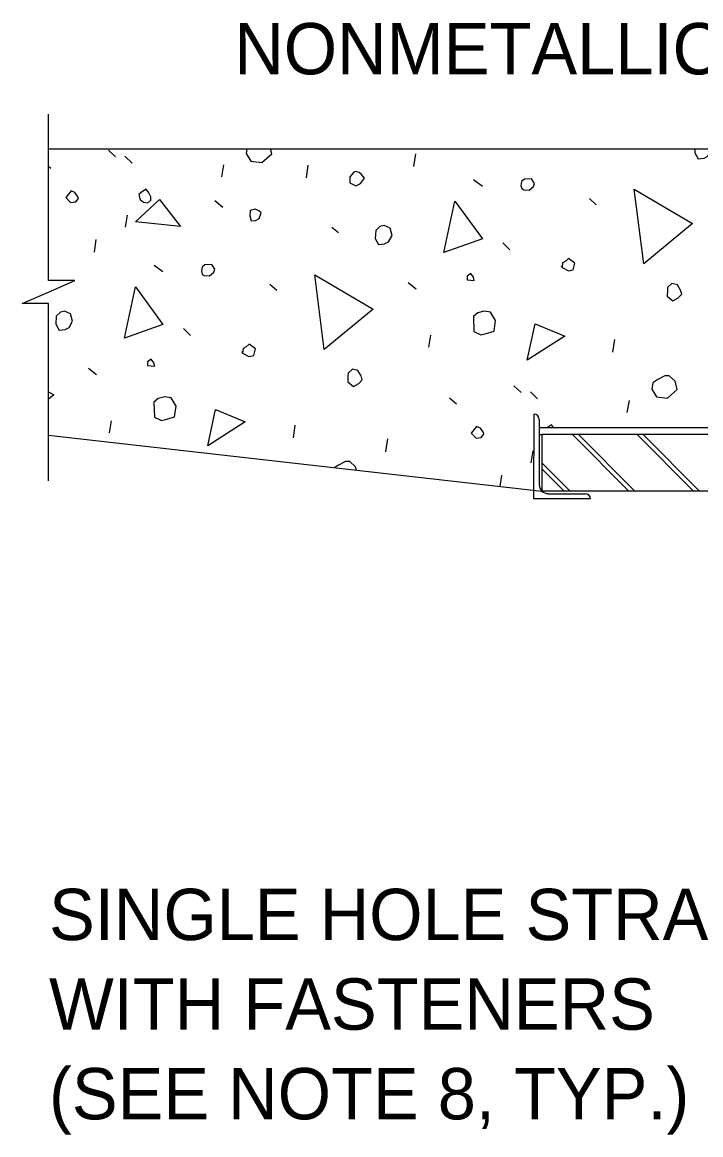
# Model space of a CAD drawing. Extents: x -1660015.2 to -1659984.9, y 2580594.2 to 2580616.7.
# Drawn here: x -1660015.124 to -1660013.123, y 2580601.152 to 2580604.429 of the extents above; entities that cross this region are included whole.
import ezdxf

# ---------------------------------------------------------------- set-up
doc = ezdxf.new("R2010")
doc.units = 0
for name, color, linetype in [('Miscellaneous', 7, 'Continuous'), ('Miscellaneous3', 7, 'Continuous'), ('PlotBorder_dp', 7, 'Continuous'), ('SheetLines_dp', 7, 'Continuous'), ('SteelGirder', 7, 'Continuous')]:
    doc.layers.add(name, color=color, linetype=linetype)

msp = doc.modelspace()

# ---------------------------------------------------------------- linework, layer by layer
at = {"layer": 'Miscellaneous'}
for p, q in [((-1660014.8697, 2580604.0526), (-1660014.8487, 2580604.0323)), ((-1660014.8209, 2580604.0346), (-1660014.7999, 2580604.0144)), ((-1660013.9689, 2580604.0041), (-1660013.9635, 2580604.0418)), ((-1660015.0462, 2580604.0056), (-1660015.0392, 2580603.9994)), ((-1660014.5354, 2580603.9739), (-1660014.5294, 2580604.0092)), ((-1660014.2861, 2580603.9709), (-1660014.2807, 2580604.0085)), ((-1660013.793, 2580603.9658), (-1660013.7673, 2580603.9468)), ((-1660014.5555, 2580603.9039), (-1660014.5321, 2580603.8842)), ((-1660013.4519, 2580603.9097), (-1660013.4316, 2580603.8918)), ((-1660014.8192, 2580603.8254), (-1660014.8131, 2580603.8607)), ((-1660014.2109, 2580603.8254), (-1660014.1913, 2580603.8099)), ((-1660014.9107, 2580603.7517), (-1660014.9053, 2580603.7894)), ((-1660013.7068, 2580603.7793), (-1660013.6859, 2580603.759)), ((-1660014.7348, 2580603.7135), (-1660014.709, 2580603.6945)), ((-1660014.3937, 2580603.6573), (-1660014.3734, 2580603.6395)), ((-1660013.9862, 2580603.663), (-1660013.9629, 2580603.6434)), ((-1660014.6486, 2580603.5269), (-1660014.6276, 2580603.5066)), ((-1660013.9248, 2580603.4724), (-1660013.9187, 2580603.5077)), ((-1660013.3824, 2580603.4573), (-1660013.377, 2580603.4949)), ((-1660014.928, 2580603.4106), (-1660014.9046, 2580603.391)), ((-1660013.6743, 2580603.3583), (-1660013.6533, 2580603.3381)), ((-1660013.6255, 2580603.3404), (-1660013.6045, 2580603.3201)), ((-1660013.8641, 2580603.323), (-1660013.8438, 2580603.3052)), ((-1660013.34, 2580603.2797), (-1660013.3339, 2580603.3149)), ((-1660013.6151, 2580603.0247), (-1660013.615, 2580603.2747)), ((-1660014.8666, 2580603.22), (-1660014.8605, 2580603.2553)), ((-1660014.3242, 2580603.2049), (-1660014.3188, 2580603.2426)), ((-1660013.5994, 2580603.2591), (-1660013.5994, 2580603.0664)), ((-1660013.5994, 2580603.2354), (-1660012.0917, 2580603.2354)), ((-1660013.5994, 2580603.2146), (-1660013.5918, 2580603.2146)), ((-1660013.3353, 2580603.0479), (-1660013.502, 2580603.2147)), ((-1660013.3176, 2580603.0479), (-1660013.4843, 2580603.2147)), ((-1660013.1444, 2580603.0479), (-1660013.3111, 2580603.2147)), ((-1660013.1267, 2580603.0479), (-1660013.2934, 2580603.2147)), ((-1660014.0518, 2580603.164), (-1660014.0464, 2580603.2017)), ((-1660013.6238, 2580603.1312), (-1660013.6177, 2580603.1665)), ((-1660013.5085, 2580603.0479), (-1660013.5918, 2580603.1312)), ((-1660013.5262, 2580603.0479), (-1660013.5918, 2580603.1135)), ((-1660013.7147, 2580603.0619), (-1660013.7099, 2580603.0952)), ((-1660013.4484, 2580603.0247), (-1660013.6151, 2580603.0247)), ((-1660013.5734, 2580603.0403), (-1660013.464, 2580603.0403))]:
    msp.add_line(p, q, dxfattribs=at)
for points in [[(-1660014.4632, 2580604.0425), (-1660014.4495, 2580604.0203), (-1660014.4173, 2580604.0159), (-1660014.388, 2580604.0419), (-1660014.3918, 2580604.0559)], [(-1660014.4613, 2580604.0559), (-1660014.4632, 2580604.0425)], [(-1660013.1406, 2580604.0559), (-1660013.1412, 2580604.0447), (-1660013.1312, 2580604.0267), (-1660013.1137, 2580604.0288), (-1660013.1023, 2580604.0344), (-1660013.0917, 2580604.0528), (-1660013.0925, 2580604.0559)], [(-1660014.1576, 2580603.9742), (-1660014.1579, 2580603.956), (-1660014.1402, 2580603.9478), (-1660014.1264, 2580603.9541), (-1660014.1151, 2580603.9701), (-1660014.1232, 2580603.9809), (-1660014.13, 2580603.9868), (-1660014.1409, 2580603.9891), (-1660014.1457, 2580603.9878), (-1660014.1576, 2580603.9742)], [(-1660013.6513, 2580603.9391), (-1660013.6452, 2580603.9355), (-1660013.6294, 2580603.9346), (-1660013.6168, 2580603.9457), (-1660013.614, 2580603.9543), (-1660013.6227, 2580603.9675), (-1660013.6433, 2580603.9671), (-1660013.6516, 2580603.9597), (-1660013.6539, 2580603.9487), (-1660013.6513, 2580603.9391)], [(-1660014.9953, 2580603.9128), (-1660014.9811, 2580603.8985), (-1660014.966, 2580603.9), (-1660014.9583, 2580603.9098), (-1660014.9595, 2580603.9146), (-1660014.9683, 2580603.9278), (-1660014.9799, 2580603.9325), (-1660014.9876, 2580603.9227), (-1660014.9953, 2580603.9128)], [(-1660014.7763, 2580603.9068), (-1660014.7664, 2580603.8991), (-1660014.7531, 2580603.8975), (-1660014.7447, 2580603.9049), (-1660014.7449, 2580603.9152), (-1660014.7505, 2580603.9267), (-1660014.7586, 2580603.9374), (-1660014.7718, 2580603.9287), (-1660014.7802, 2580603.9213), (-1660014.7763, 2580603.9068)], [(-1660013.2916, 2580603.7171), (-1660013.3196, 2580603.9374), (-1660013.1474, 2580603.836), (-1660013.2916, 2580603.7171)], [(-1660014.7897, 2580603.8411), (-1660014.7193, 2580603.9066), (-1660014.6567, 2580603.8276), (-1660014.7897, 2580603.8411)], [(-1660013.8804, 2580603.7509), (-1660013.8484, 2580603.9018), (-1660013.7671, 2580603.7916), (-1660013.8804, 2580603.7509)], [(-1660014.4529, 2580603.8589), (-1660014.449, 2580603.8444), (-1660014.4362, 2580603.8452), (-1660014.4248, 2580603.8509), (-1660014.419, 2580603.8679), (-1660014.4258, 2580603.8739), (-1660014.4374, 2580603.8786), (-1660014.4519, 2580603.8747), (-1660014.4529, 2580603.8589)], [(-1660014.0816, 2580603.816), (-1660014.083, 2580603.7923), (-1660014.073, 2580603.7743), (-1660014.0555, 2580603.7764), (-1660014.044, 2580603.7821), (-1660014.0334, 2580603.8005), (-1660014.0393, 2580603.8222), (-1660014.057, 2580603.8304), (-1660014.0691, 2580603.8271), (-1660014.0816, 2580603.816)], [(-1660013.5322, 2580603.707), (-1660013.5138, 2580603.6964), (-1660013.4993, 2580603.7003), (-1660013.4942, 2580603.7198), (-1660013.5132, 2580603.7328), (-1660013.5216, 2580603.7254), (-1660013.5306, 2580603.7204), (-1660013.5322, 2580603.707), (-1660013.5335, 2580603.7118)], [(-1660014.5931, 2580603.6867), (-1660014.5869, 2580603.6832), (-1660014.5712, 2580603.6822), (-1660014.5586, 2580603.6934), (-1660014.5557, 2580603.7019), (-1660014.5644, 2580603.7151), (-1660014.5851, 2580603.7148), (-1660014.5934, 2580603.7073), (-1660014.5957, 2580603.6964), (-1660014.5931, 2580603.6867)], [(-1660014.2334, 2580603.4648), (-1660014.2613, 2580603.685), (-1660014.0892, 2580603.5836), (-1660014.2334, 2580603.4648)], [(-1660013.8123, 2580603.6708), (-1660013.7911, 2580603.6687), (-1660013.7937, 2580603.6783), (-1660013.8017, 2580603.6891), (-1660013.8125, 2580603.6811), (-1660013.8123, 2580603.6708)], [(-1660014.8222, 2580603.4985), (-1660014.7901, 2580603.6495), (-1660014.7088, 2580603.5392), (-1660014.8222, 2580603.4985)], [(-1660013.2218, 2580603.6401), (-1660013.2221, 2580603.6219), (-1660013.2055, 2580603.6082), (-1660013.1899, 2580603.6176), (-1660013.1797, 2580603.628), (-1660013.183, 2580603.6401), (-1660013.1923, 2580603.6557), (-1660013.2087, 2580603.6591), (-1660013.2213, 2580603.648), (-1660013.2218, 2580603.6401)], [(-1660015.0234, 2580603.5637), (-1660015.0248, 2580603.54), (-1660015.0148, 2580603.522), (-1660014.9972, 2580603.5241), (-1660014.9858, 2580603.5297), (-1660014.9752, 2580603.5481), (-1660014.981, 2580603.5698), (-1660014.9988, 2580603.578), (-1660015.0108, 2580603.5748), (-1660015.0234, 2580603.5637)], [(-1660013.7935, 2580603.5619), (-1660013.7922, 2580603.5183), (-1660013.7714, 2580603.5083), (-1660013.7593, 2580603.5116), (-1660013.7328, 2580603.5187), (-1660013.7284, 2580603.5509), (-1660013.7428, 2580603.5755), (-1660013.7617, 2580603.5782), (-1660013.781, 2580603.573), (-1660013.7935, 2580603.5619)], [(-1660013.6349, 2580603.4336), (-1660013.6118, 2580603.5407), (-1660013.5245, 2580603.5046), (-1660013.6349, 2580603.4336)], [(-1660014.4739, 2580603.4547), (-1660014.4556, 2580603.444), (-1660014.4411, 2580603.4479), (-1660014.436, 2580603.4674), (-1660014.455, 2580603.4804), (-1660014.4633, 2580603.473), (-1660014.4724, 2580603.468), (-1660014.4739, 2580603.4547), (-1660014.4752, 2580603.4595)], [(-1660014.7541, 2580603.4184), (-1660014.7329, 2580603.4163), (-1660014.7354, 2580603.426), (-1660014.7435, 2580603.4368), (-1660014.7543, 2580603.4287), (-1660014.7541, 2580603.4184)], [(-1660014.1635, 2580603.3877), (-1660014.1638, 2580603.3695), (-1660014.1472, 2580603.3558), (-1660014.1316, 2580603.3652), (-1660014.1215, 2580603.3757), (-1660014.1247, 2580603.3878), (-1660014.1341, 2580603.4034), (-1660014.1505, 2580603.4067), (-1660014.1631, 2580603.3956), (-1660014.1635, 2580603.3877)], [(-1660013.2678, 2580603.3482), (-1660013.2541, 2580603.326), (-1660013.2219, 2580603.3217), (-1660013.1926, 2580603.3476), (-1660013.1991, 2580603.3718), (-1660013.2163, 2580603.3879), (-1660013.229, 2580603.3871), (-1660013.2495, 2580603.3764), (-1660013.2651, 2580603.367), (-1660013.2678, 2580603.3482)], [(-1660015.0462, 2580603.3402), (-1660015.031, 2580603.3313), (-1660015.0462, 2580603.3187)], [(-1660014.7353, 2580603.3096), (-1660014.734, 2580603.2659), (-1660014.7132, 2580603.256), (-1660014.7011, 2580603.2592), (-1660014.6745, 2580603.2663), (-1660014.6702, 2580603.2985), (-1660014.6846, 2580603.3232), (-1660014.7034, 2580603.3259), (-1660014.7228, 2580603.3207), (-1660014.7353, 2580603.3096)], [(-1660014.5767, 2580603.1812), (-1660014.5536, 2580603.2884), (-1660014.4663, 2580603.2522), (-1660014.5767, 2580603.1812)], [(-1660013.5574, 2580603.2354), (-1660013.5632, 2580603.2432), (-1660013.5749, 2580603.2354)], [(-1660013.7999, 2580603.2186), (-1660013.7857, 2580603.2043), (-1660013.7706, 2580603.2057), (-1660013.7628, 2580603.2156), (-1660013.7641, 2580603.2204), (-1660013.7728, 2580603.2336), (-1660013.7844, 2580603.2382), (-1660013.7922, 2580603.2284), (-1660013.7999, 2580603.2186)], [(-1660014.1383, 2580603.11), (-1660014.1408, 2580603.1194), (-1660014.1581, 2580603.1355), (-1660014.1708, 2580603.1347), (-1660014.1912, 2580603.1241), (-1660014.2025, 2580603.1173)]]:
    msp.add_lwpolyline(points, dxfattribs=at)
for centre, radius, start, end in [((-1660013.615, 2580603.2591), 0.0156, 359.9953, 89.9953), ((-1660013.5734, 2580603.0664), 0.026, 179.9953, 269.9953), ((-1660013.464, 2580603.0247), 0.0156, 359.9953, 89.9953)]:
    msp.add_arc(centre, radius, start, end, dxfattribs=at)
at = {"layer": 'Miscellaneous3'}
for p, q in [((-1660015.0462, 2580604.0559), (-1660006.558, 2580604.056)), ((-1660015.0462, 2580603.2131), (-1660013.5918, 2580603.0479))]:
    msp.add_line(p, q, dxfattribs=at)
at = {"layer": 'SheetLines_dp'}
msp.add_lwpolyline([(-1660015.0462, 2580603.0785), (-1660015.0462, 2580603.6007), (-1660015.1237, 2580603.6007), (-1660015.0462, 2580603.6345), (-1660014.9687, 2580603.6682), (-1660015.0462, 2580603.6682), (-1660015.0462, 2580604.1586)], dxfattribs=at)
at = {"layer": 'SteelGirder'}
for p, q in [((-1660013.5918, 2580603.2146), (-1660013.5918, 2580603.0479)), ((-1660012.0918, 2580603.2146), (-1660013.5918, 2580603.2146)), ((-1660012.0918, 2580603.0479), (-1660013.5918, 2580603.0479))]:
    msp.add_line(p, q, dxfattribs=at)

# ---------------------------------------------------------------- texts
at = {"layer": 'PlotBorder_dp'}
msp.add_text('NONMETALLIC JUNCTION BOX', height=0.1512, dxfattribs=at).set_placement((-1660014.4987, 2580604.2758))
at = {"layer": 'SheetLines_dp'}
for s, p in [('SINGLE HOLE STRAPS', (-1660015.0447, 2580601.725)), ('WITH FASTENERS', (-1660015.0447, 2580601.461)), ('(SEE NOTE 8, TYP.)', (-1660015.0447, 2580601.197))]:
    msp.add_text(s, height=0.1512, dxfattribs=at).set_placement(p)

doc.saveas('drawing.dxf')
